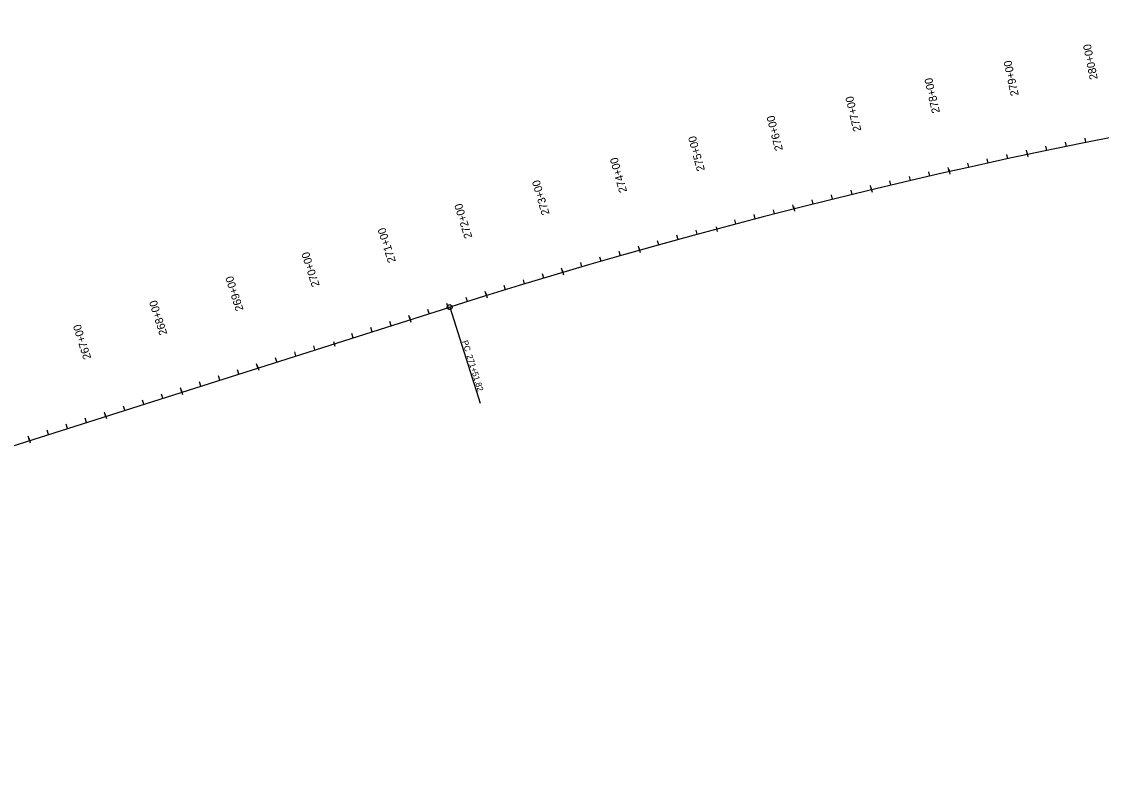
# Model space of a CAD drawing. Extents: x 20524607 to 20530050, y 8067105 to 8068411.
# Drawn here: x 20525980 to 20527332, y 8067231 to 8068193 of the extents above; entities that cross this region are included whole.
import ezdxf

# ---------------------------------------------------------------- set-up
doc = ezdxf.new("R2010")
doc.units = 0
for name, color, linetype in [('Contours Major', 7, 'Continuous'), ('Default', 7, 'Continuous'), ('Draft_DNC', 7, 'Continuous'), ('LiDAR', 7, 'Continuous'), ('Terrain', 7, 'Continuous')]:
    doc.layers.add(name, color=color, linetype=linetype)

msp = doc.modelspace()

# ---------------------------------------------------------------- linework, layer by layer
at = {"layer": 'Contours Major'}
for p, q in [((20527238.9, 8068026.7), (20527237.7, 8068032)), ((20527141.2, 8068005.3), (20527140, 8068010.6)), ((20527043.8, 8067982.6), (20527042.5, 8067987.9)), ((20526946.7, 8067958.6), (20526945.4, 8067963.9)), ((20526849.2, 8067936.4), (20526850.7, 8067930.5)), ((20526753.5, 8067906.9), (20526752, 8067912.2)), ((20526657.5, 8067879.2), (20526655.9, 8067884.4)), ((20526561.8, 8067850.2), (20526560.1, 8067855.4)), ((20526466.4, 8067820.1), (20526464.7, 8067825.3)), ((20526370.2, 8067792.7), (20526372, 8067786.9)), ((20526275.8, 8067759.6), (20526274.1, 8067764.8)), ((20526180.4, 8067729.3), (20526178.8, 8067734.6)), ((20526085.1, 8067699.1), (20526083.5, 8067704.3)), ((20525989.8, 8067668.9), (20525988.2, 8067674.1))]:
    msp.add_line(p, q, dxfattribs=at)
at = {"layer": 'Default'}
msp.add_line((20524609.4, 8067231), (20526515.8, 8067835.7), dxfattribs=at)
msp.add_arc((20528823.8, 8060560.6), 7632.4, 85.82989, 107.60125, dxfattribs=at)
at = {"layer": 'Draft_DNC'}
for p in [(20526515.8, 8067835.7), (20526553.9, 8067715.6)]:
    msp.add_line(p, (20526553.9, 8067715.6), dxfattribs=at)
msp.add_circle((20526515.8, 8067835.7), 3.12, dxfattribs=at)
at = {"layer": 'LiDAR'}
for p, q in [((20527312.3, 8068041.9), (20527311.2, 8068047.3)), ((20527263.3, 8068031.8), (20527262.2, 8068037.2)), ((20527287.8, 8068036.9), (20527286.7, 8068042.3)), ((20527190, 8068016.1), (20527188.8, 8068021.5)), ((20527214.4, 8068021.5), (20527213.3, 8068026.8)), ((20527238.2, 8068029.7), (20527239.5, 8068023.7)), ((20527116.8, 8067999.7), (20527115.6, 8068005.1)), ((20527140.5, 8068008.3), (20527141.9, 8068002.3)), ((20527165.6, 8068010.8), (20527164.4, 8068016.1)), ((20527068.1, 8067988.4), (20527066.9, 8067993.7)), ((20527092.5, 8067994.1), (20527091.2, 8067999.4)), ((20526995.2, 8067970.8), (20526993.9, 8067976.1)), ((20527019.5, 8067976.7), (20527018.2, 8067982)), ((20527043.1, 8067985.6), (20527044.5, 8067979.6)), ((20526971, 8067964.7), (20526969.6, 8067970)), ((20526898.3, 8067946.2), (20526896.9, 8067951.5)), ((20526922.5, 8067952.5), (20526921.1, 8067957.7)), ((20526946, 8067961.6), (20526947.5, 8067955.7)), ((20526849.2, 8067936.4), (20526850.7, 8067930.5)), ((20526874.1, 8067939.8), (20526872.7, 8067945.1)), ((20526801.7, 8067920.3), (20526800.3, 8067925.6)), ((20526825.8, 8067926.9), (20526824.4, 8067932.2)), ((20526752.7, 8067909.9), (20526754.4, 8067904)), ((20526777.6, 8067913.7), (20526776.1, 8067918.9)), ((20526705.4, 8067893.2), (20526703.9, 8067898.4)), ((20526729.5, 8067900.1), (20526728, 8067905.4)), ((20526656.6, 8067882.1), (20526658.3, 8067876.2)), ((20526681.4, 8067886.2), (20526679.9, 8067891.5)), ((20526609.6, 8067864.8), (20526608, 8067870)), ((20526633.5, 8067872), (20526631.9, 8067877.3)), ((20526585.6, 8067857.5), (20526584, 8067862.7)), ((20526537.9, 8067842.7), (20526536.3, 8067847.9)), ((20526560.9, 8067853.1), (20526562.7, 8067847.2)), ((20526490.2, 8067827.6), (20526488.6, 8067832.8)), ((20526514.1, 8067835.2), (20526512.4, 8067840.4)), ((20526442.6, 8067812.5), (20526440.9, 8067817.7)), ((20526465.5, 8067823), (20526467.3, 8067817.1)), ((20526394.9, 8067797.4), (20526393.3, 8067802.6)), ((20526418.7, 8067804.9), (20526417.1, 8067810.1)), ((20526347.2, 8067782.3), (20526345.6, 8067787.5)), ((20526370.2, 8067792.7), (20526372, 8067786.9)), ((20526323.4, 8067774.7), (20526321.8, 8067779.9)), ((20526274.8, 8067762.5), (20526276.7, 8067756.7)), ((20526299.6, 8067767.1), (20526297.9, 8067772.3)), ((20526228.1, 8067744.5), (20526226.4, 8067749.7)), ((20526251.9, 8067752), (20526250.3, 8067757.2)), ((20526204.3, 8067736.9), (20526202.6, 8067742.1)), ((20526132.8, 8067714.2), (20526131.1, 8067719.4)), ((20526156.6, 8067721.8), (20526155, 8067727)), ((20526179.5, 8067732.3), (20526181.4, 8067726.4)), ((20526109, 8067706.7), (20526107.3, 8067711.9)), ((20526061.3, 8067691.5), (20526059.6, 8067696.8)), ((20526084.2, 8067702), (20526086, 8067696.2)), ((20526013.6, 8067676.4), (20526012, 8067681.6)), ((20526037.5, 8067684), (20526035.8, 8067689.2)), ((20525988.9, 8067671.8), (20525990.7, 8067666))]:
    msp.add_line(p, q, dxfattribs=at)
at = {"layer": 'Terrain'}
msp.add_line((20524609.4, 8067231), (20526515.8, 8067835.7), dxfattribs=at)
msp.add_arc((20528823.8, 8060560.6), 7632.4, 85.82989, 107.60125, dxfattribs=at)

# ---------------------------------------------------------------- texts
at = {"layer": 'Contours Major'}
for s, rotation, p in [('280+00', 101.2341, (20527327.1, 8068121.4)), ('275+00', 104.9875, (20526835.4, 8068007.2)), ('270+00', 107.6013, (20526353.2, 8067862.8))]:
    msp.add_text(s, height=10.02, rotation=rotation, dxfattribs=at).set_placement(p)
at = {"layer": 'Draft_DNC'}
for s, p in [('PC', (20526531.1, 8067792.8)), ('271+51.82', (20526536.8, 8067775))]:
    msp.add_text(s, height=7.5, rotation=287.6013, dxfattribs=at).set_placement(p)
at = {"layer": 'LiDAR'}
for s, rotation, p in [('280+00', 101.2341, (20527327.1, 8068121.4)), ('279+00', 101.9847, (20527228.2, 8068101.1)), ('278+00', 102.7354, (20527129.6, 8068079.5)), ('277+00', 103.4861, (20527031.2, 8068056.7)), ('276+00', 104.2368, (20526933.1, 8068032.6)), ('275+00', 104.9875, (20526835.4, 8068007.2)), ('274+00', 105.7382, (20526738, 8067980.5)), ('273+00', 106.4889, (20526641, 8067952.5)), ('272+00', 107.2396, (20526544.3, 8067923.3)), ('271+00', 107.6013, (20526448.5, 8067893.1)), ('270+00', 107.6013, (20526353.2, 8067862.8)), ('269+00', 107.6013, (20526257.9, 8067832.6)), ('268+00', 107.6013, (20526162.5, 8067802.3)), ('267+00', 107.6013, (20526067.2, 8067772.1))]:
    msp.add_text(s, height=10.02, rotation=rotation, dxfattribs=at).set_placement(p)

doc.saveas('drawing.dxf')
